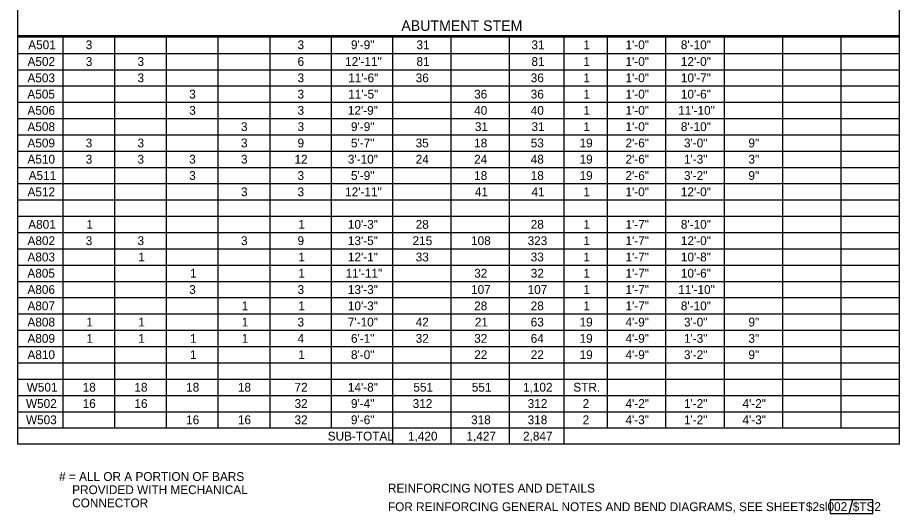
# Model space of a CAD drawing. Extents: x -18.5 to 33.3, y 0.6 to 37.5.
# Drawn here: x 1.71 to 15.71, y 0.81 to 8.69 of the extents above; entities that cross this region are included whole.
import ezdxf

# ---------------------------------------------------------------- set-up
doc = ezdxf.new("R2010")
doc.units = 0
doc.layers.add('BR_X_Beam_Centerline', color=7, linetype='Continuous')
doc.layers.add('Default', color=7, linetype='Continuous')

msp = doc.modelspace()

# ---------------------------------------------------------------- linework, layer by layer
at = {"layer": 'BR_X_Beam_Centerline'}
msp.add_line((14.919, 0.814), (14.974, 1.029), dxfattribs=at)
msp.add_lwpolyline([(14.618, 0.814), (15.292, 0.814), (15.292, 1.029), (14.618, 1.029)], close=True, dxfattribs=at)
at = {"layer": 'Default'}
for p, q in [((15.714, 1.913), (15.714, 20.614)), ((1.715, 19.468), (1.715, 8.385)), ((1.715, 8.405), (15.714, 8.405)), ((1.715, 8.405), (1.715, 1.913)), ((5.717, 8.405), (5.717, 2.171)), ((9.521, 8.405), (9.521, 1.913)), ((1.715, 8.385), (15.714, 8.385)), ((2.43, 8.385), (2.43, 2.171)), ((3.252, 8.385), (3.252, 2.171)), ((4.073, 8.385), (4.073, 2.171)), ((4.895, 8.385), (4.895, 2.171)), ((6.691, 8.385), (6.691, 2.171)), ((7.665, 8.385), (7.665, 1.913)), ((8.593, 8.385), (8.593, 1.913)), ((10.388, 8.385), (10.388, 1.913)), ((11.073, 8.385), (11.073, 2.171)), ((12.001, 8.385), (12.001, 2.171)), ((12.93, 8.385), (12.93, 2.171)), ((13.858, 8.385), (13.858, 2.171)), ((14.786, 8.385), (14.786, 2.171)), ((1.715, 8.121), (15.714, 8.121)), ((1.715, 7.862), (15.714, 7.862)), ((1.715, 7.604), (15.714, 7.604)), ((1.715, 7.345), (15.714, 7.345)), ((1.715, 7.086), (15.714, 7.086)), ((1.715, 6.828), (15.714, 6.828)), ((1.715, 6.569), (15.714, 6.569)), ((1.715, 6.31), (15.714, 6.31)), ((1.715, 6.052), (15.714, 6.052)), ((1.715, 5.793), (15.714, 5.793)), ((1.715, 5.534), (15.714, 5.534)), ((1.715, 5.275), (15.714, 5.275)), ((1.715, 5.017), (15.714, 5.017)), ((1.715, 4.758), (15.714, 4.758)), ((1.715, 4.499), (15.714, 4.499)), ((1.715, 4.241), (15.714, 4.241)), ((1.715, 3.982), (15.714, 3.982)), ((1.715, 3.723), (15.714, 3.723)), ((1.715, 3.465), (15.714, 3.465)), ((1.715, 3.206), (15.714, 3.206)), ((1.715, 2.947), (15.714, 2.947)), ((1.715, 2.689), (15.714, 2.689)), ((1.715, 2.43), (15.714, 2.43)), ((1.715, 2.171), (15.714, 2.171)), ((15.714, 1.913), (1.715, 1.913))]:
    msp.add_line(p, q, dxfattribs=at)

# ---------------------------------------------------------------- texts
at = {"layer": 'BR_X_Beam_Centerline'}
for s, height, p in [('ABUTMENT STEM', 0.16799, (7.807, 8.478)), ('A501', 0.14, (1.883, 8.188)), ('3', 0.14, (2.796, 8.188)), ('3', 0.14, (6.159, 8.188)), ('9\'-9"', 0.14, (7.007, 8.188)), ('31', 0.14, (8.047, 8.188)), ('31', 0.14, (9.873, 8.188)), ('1', 0.14, (10.698, 8.188)), ('1\'-0"', 0.14, (11.366, 8.188)), ('8\'-10"', 0.14, (12.245, 8.188)), ('A502', 0.14, (1.872, 7.922)), ('3', 0.14, (2.796, 7.922)), ('3', 0.14, (3.618, 7.922)), ('6', 0.14, (6.159, 7.922)), ('12\'-11"', 0.14, (6.915, 7.922)), ('81', 0.14, (8.047, 7.922)), ('81', 0.14, (9.873, 7.922)), ('1', 0.14, (10.698, 7.922)), ('1\'-0"', 0.14, (11.366, 7.922)), ('12\'-0"', 0.14, (12.245, 7.922)), ('A503', 0.14, (1.871, 7.663)), ('3', 0.14, (3.618, 7.663)), ('3', 0.14, (6.159, 7.663)), ('11\'-6"', 0.14, (6.964, 7.663)), ('36', 0.14, (8.035, 7.663)), ('36', 0.14, (9.861, 7.663)), ('1', 0.14, (10.698, 7.663)), ('1\'-0"', 0.14, (11.366, 7.663)), ('10\'-7"', 0.14, (12.245, 7.663)), ('A505', 0.14, (1.87, 7.404)), ('3', 0.14, (4.439, 7.404)), ('3', 0.14, (6.159, 7.404)), ('11\'-5"', 0.14, (6.964, 7.404)), ('36', 0.14, (8.963, 7.404)), ('36', 0.14, (9.861, 7.404)), ('1', 0.14, (10.698, 7.404)), ('1\'-0"', 0.14, (11.366, 7.404)), ('10\'-6"', 0.14, (12.245, 7.404)), ('A506', 0.14, (1.871, 7.146)), ('3', 0.14, (4.439, 7.146)), ('3', 0.14, (6.159, 7.146)), ('12\'-9"', 0.14, (6.958, 7.146)), ('40', 0.14, (8.963, 7.146)), ('40', 0.14, (9.861, 7.146)), ('1', 0.14, (10.698, 7.146)), ('1\'-0"', 0.14, (11.366, 7.146)), ('11\'-10"', 0.14, (12.203, 7.146)), ('A508', 0.14, (1.871, 6.887)), ('3', 0.14, (5.261, 6.887)), ('3', 0.14, (6.159, 6.887)), ('9\'-9"', 0.14, (7.007, 6.887)), ('31', 0.14, (8.975, 6.887)), ('31', 0.14, (9.873, 6.887)), ('1', 0.14, (10.698, 6.887)), ('1\'-0"', 0.14, (11.366, 6.887)), ('8\'-10"', 0.14, (12.245, 6.887)), ('A509', 0.14, (1.871, 6.628)), ('3', 0.14, (2.796, 6.628)), ('3', 0.14, (3.618, 6.628)), ('3', 0.14, (5.261, 6.628)), ('9', 0.14, (6.159, 6.628)), ('5\'-7"', 0.14, (7.007, 6.628)), ('35', 0.14, (8.034, 6.628)), ('18', 0.14, (8.963, 6.628)), ('53', 0.14, (9.861, 6.628)), ('19', 0.14, (10.637, 6.628)), ('2\'-6"', 0.14, (11.366, 6.628)), ('3\'-0"', 0.14, (12.294, 6.628)), ('9"', 0.14, (13.318, 6.628)), ('A510', 0.14, (1.871, 6.37)), ('3', 0.14, (2.796, 6.37)), ('3', 0.14, (3.618, 6.37)), ('3', 0.14, (4.439, 6.37)), ('3', 0.14, (5.261, 6.37)), ('12', 0.14, (6.111, 6.37)), ('3\'-10"', 0.14, (6.958, 6.37)), ('24', 0.14, (8.035, 6.37)), ('24', 0.14, (8.963, 6.37)), ('48', 0.14, (9.861, 6.37)), ('19', 0.14, (10.637, 6.37)), ('2\'-6"', 0.14, (11.366, 6.37)), ('1\'-3"', 0.14, (12.294, 6.37)), ('3"', 0.14, (13.318, 6.37)), ('A511', 0.14, (1.89, 6.111)), ('3', 0.14, (4.439, 6.111)), ('3', 0.14, (6.159, 6.111)), ('5\'-9"', 0.14, (7.007, 6.111)), ('18', 0.14, (8.963, 6.111)), ('18', 0.14, (9.861, 6.111)), ('19', 0.14, (10.637, 6.111)), ('2\'-6"', 0.14, (11.366, 6.111)), ('3\'-2"', 0.14, (12.294, 6.111)), ('9"', 0.14, (13.318, 6.111)), ('A512', 0.14, (1.872, 5.852)), ('3', 0.14, (5.261, 5.852)), ('3', 0.14, (6.159, 5.852)), ('12\'-11"', 0.14, (6.915, 5.852)), ('41', 0.14, (8.975, 5.852)), ('41', 0.14, (9.873, 5.852)), ('1', 0.14, (10.698, 5.852)), ('1\'-0"', 0.14, (11.366, 5.852)), ('12\'-0"', 0.14, (12.245, 5.852)), ('A801', 0.14, (1.883, 5.335)), ('1', 0.14, (2.808, 5.335)), ('1', 0.14, (6.171, 5.335)), ('10\'-3"', 0.14, (6.958, 5.335)), ('28', 0.14, (8.035, 5.335)), ('28', 0.14, (9.861, 5.335)), ('1', 0.14, (10.698, 5.335)), ('1\'-7"', 0.14, (11.366, 5.335)), ('8\'-10"', 0.14, (12.245, 5.335)), ('A802', 0.14, (1.872, 5.076)), ('3', 0.14, (2.796, 5.076)), ('3', 0.14, (3.618, 5.076)), ('3', 0.14, (5.261, 5.076)), ('9', 0.14, (6.159, 5.076)), ('13\'-5"', 0.14, (6.958, 5.076)), ('215', 0.14, (7.985, 5.076)), ('108', 0.14, (8.914, 5.076)), ('323', 0.14, (9.812, 5.076)), ('1', 0.14, (10.698, 5.076)), ('1\'-7"', 0.14, (11.366, 5.076)), ('12\'-0"', 0.14, (12.245, 5.076)), ('A803', 0.14, (1.871, 4.817)), ('1', 0.14, (3.63, 4.817)), ('1', 0.14, (6.171, 4.817)), ('12\'-1"', 0.14, (6.958, 4.817)), ('33', 0.14, (8.035, 4.817)), ('33', 0.14, (9.861, 4.817)), ('1', 0.14, (10.698, 4.817)), ('1\'-7"', 0.14, (11.366, 4.817)), ('10\'-8"', 0.14, (12.245, 4.817)), ('A805', 0.14, (1.87, 4.559)), ('1', 0.14, (4.452, 4.559)), ('1', 0.14, (6.171, 4.559)), ('11\'-11"', 0.14, (6.922, 4.559)), ('32', 0.14, (8.964, 4.559)), ('32', 0.14, (9.862, 4.559)), ('1', 0.14, (10.698, 4.559)), ('1\'-7"', 0.14, (11.366, 4.559)), ('10\'-6"', 0.14, (12.245, 4.559)), ('A806', 0.14, (1.871, 4.3)), ('3', 0.14, (4.439, 4.3)), ('3', 0.14, (6.159, 4.3)), ('13\'-3"', 0.14, (6.958, 4.3)), ('107', 0.14, (8.914, 4.3)), ('107', 0.14, (9.812, 4.3)), ('1', 0.14, (10.698, 4.3)), ('1\'-7"', 0.14, (11.366, 4.3)), ('11\'-10"', 0.14, (12.203, 4.3)), ('A807', 0.14, (1.871, 4.041)), ('1', 0.14, (5.273, 4.041)), ('1', 0.14, (6.171, 4.041)), ('10\'-3"', 0.14, (6.958, 4.041)), ('28', 0.14, (8.963, 4.041)), ('28', 0.14, (9.861, 4.041)), ('1', 0.14, (10.698, 4.041)), ('1\'-7"', 0.14, (11.366, 4.041)), ('8\'-10"', 0.14, (12.245, 4.041)), ('A808', 0.14, (1.871, 3.783)), ('1', 0.14, (2.808, 3.783)), ('1', 0.14, (3.63, 3.783)), ('1', 0.14, (5.273, 3.783)), ('3', 0.14, (6.159, 3.783)), ('7\'-10"', 0.14, (6.958, 3.783)), ('42', 0.14, (8.035, 3.783)), ('21', 0.14, (8.975, 3.783)), ('63', 0.14, (9.861, 3.783)), ('19', 0.14, (10.637, 3.783)), ('4\'-9"', 0.14, (11.366, 3.783)), ('3\'-0"', 0.14, (12.294, 3.783)), ('9"', 0.14, (13.318, 3.783)), ('A809', 0.14, (1.871, 3.524)), ('1', 0.14, (2.808, 3.524)), ('1', 0.14, (3.63, 3.524)), ('1', 0.14, (4.452, 3.524)), ('1', 0.14, (5.273, 3.524)), ('4', 0.14, (6.159, 3.524)), ('6\'-1"', 0.14, (7.007, 3.524)), ('32', 0.14, (8.035, 3.524)), ('32', 0.14, (8.964, 3.524)), ('64', 0.14, (9.861, 3.524)), ('19', 0.14, (10.637, 3.524)), ('4\'-9"', 0.14, (11.366, 3.524)), ('1\'-3"', 0.14, (12.294, 3.524)), ('3"', 0.14, (13.318, 3.524)), ('A810', 0.14, (1.871, 3.265)), ('1', 0.14, (4.452, 3.265)), ('1', 0.14, (6.171, 3.265)), ('8\'-0"', 0.14, (7.007, 3.265)), ('22', 0.14, (8.964, 3.265)), ('22', 0.14, (9.862, 3.265)), ('19', 0.14, (10.637, 3.265)), ('4\'-9"', 0.14, (11.366, 3.265)), ('3\'-2"', 0.14, (12.294, 3.265)), ('9"', 0.14, (13.318, 3.265)), ('W501', 0.14, (1.859, 2.748)), ('18', 0.14, (2.747, 2.748)), ('18', 0.14, (3.569, 2.748)), ('18', 0.14, (4.39, 2.748)), ('18', 0.14, (5.212, 2.748)), ('72', 0.14, (6.111, 2.748)), ('14\'-8"', 0.14, (6.958, 2.748)), ('551', 0.14, (7.998, 2.748)), ('551', 0.14, (8.926, 2.748)), ('1,102', 0.14, (9.739, 2.748)), ('STR.', 0.14, (10.538, 2.748)), ('W502', 0.14, (1.847, 2.489)), ('16', 0.14, (2.747, 2.489)), ('16', 0.14, (3.569, 2.489)), ('32', 0.14, (6.111, 2.489)), ('9\'-4"', 0.14, (7.007, 2.489)), ('312', 0.14, (7.987, 2.489)), ('312', 0.14, (9.813, 2.489)), ('2', 0.14, (10.686, 2.489)), ('4\'-2"', 0.14, (11.366, 2.489)), ('1\'-2"', 0.14, (12.294, 2.489)), ('4\'-2"', 0.14, (13.223, 2.489)), ('W503', 0.14, (1.847, 2.231)), ('16', 0.14, (4.39, 2.231)), ('16', 0.14, (5.212, 2.231)), ('32', 0.14, (6.111, 2.231)), ('9\'-6"', 0.14, (7.007, 2.231)), ('318', 0.14, (8.914, 2.231)), ('318', 0.14, (9.812, 2.231)), ('2', 0.14, (10.686, 2.231)), ('4\'-3"', 0.14, (11.366, 2.231)), ('1\'-2"', 0.14, (12.294, 2.231)), ('4\'-3"', 0.14, (13.223, 2.231)), ('SUB-TOTAL', 0.14, (6.638, 1.972)), ('1,420', 0.14, (7.913, 1.972)), ('1,427', 0.14, (8.841, 1.972)), ('2,847', 0.14, (9.739, 1.972)), ('# = ALL OR A PORTION OF BARS ', 0.14, (2.373, 1.33)), ('    PROVIDED WITH MECHANICAL ', 0.14, (2.373, 1.12)), ('REINFORCING NOTES AND DETAILS', 0.14, (7.594, 1.145)), ('    CONNECTOR', 0.14, (2.373, 0.91)), ('FOR REINFORCING GENERAL NOTES AND BEND DIAGRAMS, SEE SHEET', 0.14, (7.594, 0.85)), ('$2sl002', 0.14, (14.23, 0.852)), ('$TS2', 0.14, (14.974, 0.852))]:
    msp.add_text(s, height=height, dxfattribs=at).set_placement(p)

doc.saveas('drawing.dxf')
